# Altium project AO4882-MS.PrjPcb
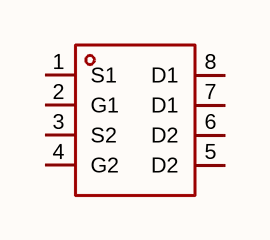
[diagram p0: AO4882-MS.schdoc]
1 sheet, 1 parts. Net scope: global (net labels, ports and power ports of the same name join across sheets).

## Sheet AO4882-MS.schdoc
size 127 x 101 mm

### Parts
Q?  ao4882-ms  [SOP-8_L4.9-W3.9-P1.27-LS6.0-TL]  (value not drawn)

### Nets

Not connected (* = marked no-connect by the designer): Q? 1(S1) 2(G1) 3(S2) 4(G2) 5(D2) 6(D2) 7(D1) 8(D1)

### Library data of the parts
Q? = ao4882-ms: 数量:2个N沟道;漏源电压(Vdss):40V;连续漏极电流(Id):6A;导通电阻(RDS(on)):30mΩ@10V;耗散功率(Pd):1.9W;阈值电压(Vgs(th)):1.2V;; Manufacturer: MSKSEMI(美森科); AddInBom: yes; ModelId: 4f1f5228684a45afaa7af8cce46001de; ModelName: SOP-8_L4.9-W3.9-H1.45-LS6.0-P1.27; ModelTransform: 236.22,189.751,0,0,0,0,-0.005,0.003,0; Number: 2个N沟道; Drain to Source Voltage: 40V; Current - Continuous Drain(Id): 6A; Pd - Power Dissipation: 1.9W; Gate Threshold Voltage (Vgs(th)): 1.2V; Gate Charge(Qg): 9.8nC@4.5V; Input Capacitance(Ciss): 1.013nF; Reverse Transfer Capacitance (Crss@Vds): 76pF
